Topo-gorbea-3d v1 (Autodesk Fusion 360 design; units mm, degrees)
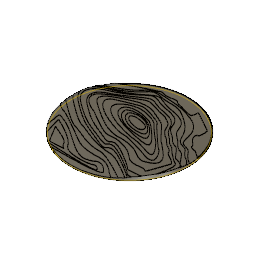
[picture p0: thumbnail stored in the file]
sketch "Sketch1"
  circle C1 centre (0, 0) radius 162.5
  dimension "d1" diameter C1 = 325
extrude "Extrude1" new body sketch "Sketch1" blind 19
sketch "gorbea-topo2" plane through (0, 0, 19) normal (0, 0, 1) x axis (1, 0, 0)
sketch "gorbea-topo2 (1)" plane through (0, 0, 19) normal (0, 0, 1) x axis (1, 0, 0)
sketch "Sketch6" plane through (0, 0, 0) normal (1, 0, 0) x axis (0, 1, 0)
extrude "Extrude2" cut sketch "gorbea-topo2 (1)" against normal blind 1
sketch "Sketch3"
extrude "Extrude3" cut sketch "gorbea-topo2 (1)" against normal blind 2
extrude "Extrude4" cut sketch "gorbea-topo2 (1)" against normal blind 3
extrude "Extrude5" cut sketch "gorbea-topo2 (1)" against normal blind 4
extrude "Extrude6" cut sketch "gorbea-topo2 (1)" against normal blind 5
extrude "Extrude7" cut sketch "gorbea-topo2 (1)" against normal blind 6
extrude "Extrude8" cut sketch "gorbea-topo2 (1)" against normal blind 7
extrude "Extrude9" cut sketch "gorbea-topo2 (1)" against normal blind 8
extrude "Extrude10" cut sketch "gorbea-topo2 (1)" against normal blind 9
extrude "Extrude11" cut sketch "gorbea-topo2 (1)" against normal blind 10
extrude "Extrude12" cut sketch "gorbea-topo2 (1)" against normal blind 11
extrude "Extrude13" cut sketch "gorbea-topo2 (1)" against normal blind 12
extrude "Extrude14" cut sketch "gorbea-topo2 (1)" against normal blind 13
extrude "Extrude15" cut sketch "gorbea-topo2 (1)" against normal blind 14
extrude "Extrude16" cut sketch "gorbea-topo2 (1)" against normal blind 15
extrude "Extrude17" cut sketch "gorbea-topo2 (1)" against normal blind 16
extrude "Extrude18" cut sketch "gorbea-topo2 (1)" against normal blind 17
extrude "Extrude19" cut of existing geometry blind -14
extrude "Extrude20" cut of existing geometry blind -14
